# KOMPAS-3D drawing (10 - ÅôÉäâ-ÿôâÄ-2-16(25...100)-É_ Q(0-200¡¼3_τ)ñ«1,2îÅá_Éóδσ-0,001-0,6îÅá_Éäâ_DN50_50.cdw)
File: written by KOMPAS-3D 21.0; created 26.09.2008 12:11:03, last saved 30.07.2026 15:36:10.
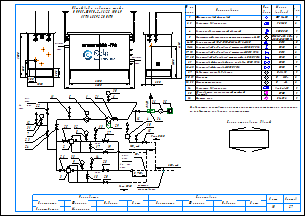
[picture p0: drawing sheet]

Sheets 1-2: A3, landscape

Document properties: Наименование: Макро:21; Автор: RaskoAdmin; Форматы листов документа: 2xA3; Полное имя файла: \\ur38nt01\Departments\КТО\КБ ПУРДГ\Заявки\Прайс-лист на типовые шкафы ГРПШ\ПУРДГ_стандарт_30_04_2026\ПУРДГ с РДГ(Н, В)\ПУРДГ-ШУГО-2-16(25...100)-Р_ Q(0-200нм3_ч)до1,2МПа_Рвых-0,001-0,6МПа_РДГ_DN50_50.cdw

Title block, sheet 1: Наименование: Пункт учета газа / ПУГ-Ш-400-Р / ЛГТИ.485922.001ТУ; designation: ЛГТИ.03.4411141; sheet number: 1; Количество листов документа: 2; organisation: ООО "ЭЛЬСТЕР Газэлектроника"; Форматы листов документа: A3; stored path: C:\Рабочие документы\Компас\ПУГ\Схема.cdw; Разработал: Устинов; Проверил: Кошкин; Утвердил: Кошкин
Title block, sheet 2: sheet number: 2; stored path: D:\Рабочие документы\Заявки\ПУРДГ\ПУРДГ-ШУЭО-2-100-Р 4411220.cdw; designation, second copy: ЛГТИ.03.4411141-

Views: Вид 1, Вид 2
Referenced files: wcvoit.frw
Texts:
  Normal
  № на
  схеме
  Усл.
  обозн.
  Марка
  (модель)
  Кол.
  Фильтр газовый фланцевый
  ФГ 16-50
  Регулятор давления газа
  РДГ-50
  Клапан предохранительный сбросной
  КПС DN20
  Измерительный комплекс с ротационным счетчиком Ду50
  СГ-ЭК-Р-(0,2...2,0)-
  Кран кнопочный VE-РАСКО-НЗ-1,6-G1/2-М20
  DN15
  Кран шаровой "под приварку" штуцерный DN20 PN16
  DN20
  Кран шаровой "под приварку" штуцерный DN15 PN16
  Кран шаровой "под приварку" штуцерный п/п DN20 PN16
  Кран шаровой фланцевый с мех. приводом DN50 PN16
  Кран шаровой фланцевый DN50 PN16
  DN50
  Индикатор перепада давления
  Манометр
  Манометр-напоромер
  Обогреватель газогорелочный шкафной
  (Эльтон")
  Счетчик газа
  Delta 15
  0...     МПа
  0...     кПа
  Venio-A-15
  ОГШН
  BK-G1,6
  Общий вид и габариты шкафа
  ПУРДГ-ШУГО-2-16(25...100)-Р
  Выход газа
  Вход газа
  logo-rasko-ge.png
  DN 1
  местное
  сопротивление
  Римп DN20
  Выход
  газа
  Р=     кПа
  Вход
  Р=       МПа
  PDI
  Схема открывания дверей
  Предприятие изготовитель может заменять комплектующие на аналогичные,
  не ухудшающие заявленных характеристик.
  Должность
  Конструктор
  Фамилия
  Подпись
  Дата
  Согласовано
  Максимкин
  Лист
  Листов
  POLYLINE_STYLE_0.18_RGB_0_0_0
  POLYLINE_STYLE_0.50_RGB_0_0_0
  POLYLINE_STYLE_0.34_RGB_0_0_0
  PHANTOM_RGB_0_0_0_SC_1_THICK_0.18
  K5LT_THIN_RGB_0_0_0_THICK_0.18
  K5LT32769_RGB_0_0_0_THICK_0.18
  K5LT12_RGB_0_0_0_SC_1_THICK_0.18
  K5LT_DASHED_RGB_0_0_0_SC_1_THICK_0.18
  ACISOTGL_RGB_0_0_0_SC_0.8_THICK_0.25
  CONTINUOUS_RGB_0_127_31_THICK_0.3
  CONTINUOUS_RGB_0_0_255_THICK_0.35
  CONTINUOUS_RGB_255_0_0_THICK_0.35
  POLYLINE_STYLE_0.25_RGB_0_0_0
  CONTINUOUS_RGB_0_0_0_THICK_0.5
  POLYLINE_STYLE_0.35_RGB_0_0_255
  CONTINUOUS_RGB_0_0_0_THICK_0.4
  CONTINUOUS_RGB_0_0_0_THICK_0.35
  НЕВИДИМАЯ_RGB_0_0_0_SC_0.3_THICK_0.25
  СONTINUOUS_RGB_0_0_0_THICK_0.25
  ОСЕВАЯ2_RGB_248_153_30_SC_0.3_THICK_0.25
  Без оформления
Dimensions and other numbers on the sheet: 1; 2, 3; 2; 4; 5; 6-10; 11-16; 6; 17, 18; 19, 20; 21; 22-28; 7; 29; 30, 31; 32, 33; 34; 35; 36; 1500; 250; 300; 1050; 550; 305; 2300; 4130; 2000; 2600; 5,,,7DN 1; 31; 12; 22; 23; 24; 11; 30; 25; 32; 8; 17; 13; 27; 19; 10; 15; 26; 33; 9; 3; 18; 14; 28; 20; 16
